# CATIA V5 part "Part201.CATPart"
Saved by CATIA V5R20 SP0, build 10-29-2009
Part number: FA 168700-3
Revision: ANY
Definition: UNKNOWN
Nomenclature: FA 168700-3
Source: Unknown
Bounding box of the stored display mesh (mm): x -3 to 3, y 0 to 4.95, z -3.464 to 3.464
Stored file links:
  C:\Users\Utente\Desktop\IO LAVORO\3D X SITO CF\CUMSA\3D files FA\FA 168712-20\Part201.CATPart

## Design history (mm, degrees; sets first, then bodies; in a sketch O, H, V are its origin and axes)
Body1 "Cortar-Extruir3" (main body)
  Solid1: solid without history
